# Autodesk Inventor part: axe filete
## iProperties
Created: 2002-03
Part Number: axe filete
Material: Par défaut
Document SubType Name: Modélisation
Designer: BAVERGE
Control State: 0
Master: False
Checked Out: False
Shininess: 20.0
Length Units: 11269
Angle Units: 11279
Time Units: 11290
Mass Units: 11283
Length Display Precision: 3
Angle Display Precision: 2
Density: 0.0
Volumn: 0.0
Area: 0.0
PropertySet Name: Model Information
Author: BAVERGE
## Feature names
1. Révolution1 [Revolution]
2. Chanfrein1 [Chamfer]
3. Extrusion1
